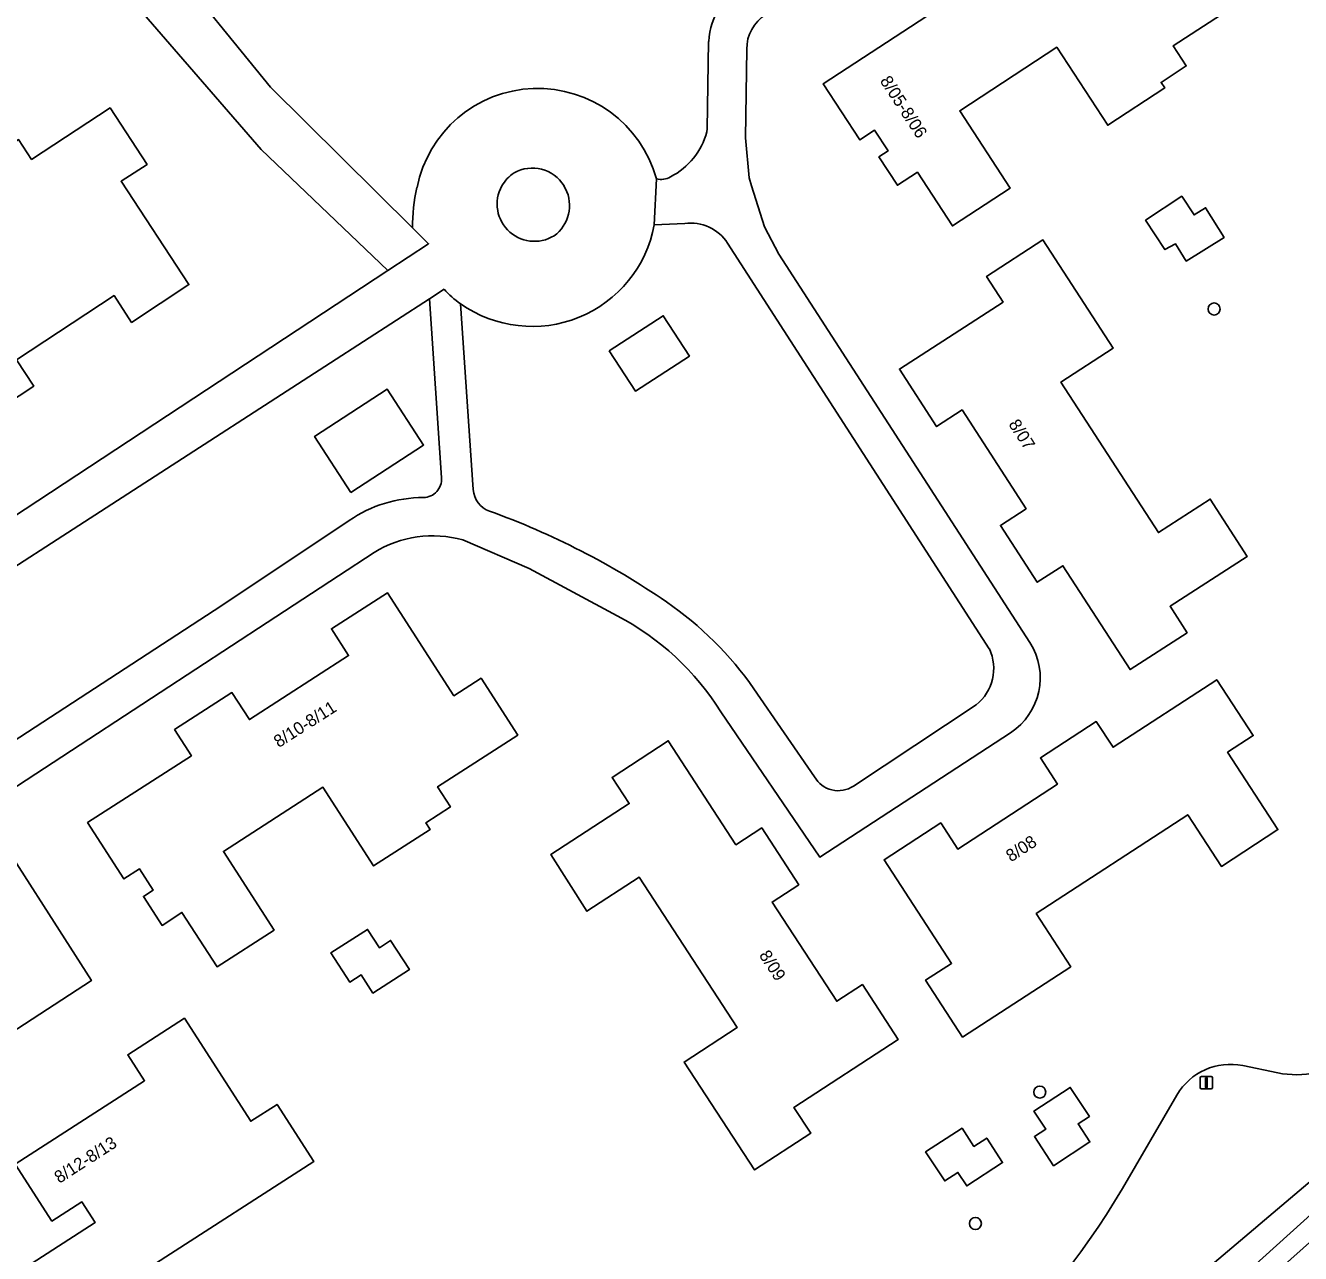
# Model space of a CAD drawing. Extents: x 159451 to 160664, y 388402 to 389723.
# Drawn here: x 160043.7 to 160146.8, y 389163.7 to 389263 of the extents above; entities that cross this region are included whole.
import ezdxf

# ---------------------------------------------------------------- set-up
doc = ezdxf.new("R2010")
doc.units = 0
for name, color, linetype in [('IMGEO_Boom', 7, 'Continuous'), ('IMGEO_Erf', 7, 'Continuous'), ('IMGEO_Grasland_overig', 7, 'Continuous'), ('IMGEO_Groenvoorziening', 7, 'Continuous'), ('IMGEO_Lichtmast', 7, 'Continuous'), ('IMGEO_Loofbos', 7, 'Continuous'), ('IMGEO_Oever', 7, 'Continuous'), ('IMGEO_Pand', 7, 'Continuous'), ('IMGEO_Pand_nummerreeks', 7, 'Continuous'), ('IMGEO_Rijbaan_lokaal_gesloten', 7, 'Continuous'), ('IMGEO_Rijbaan_lokaal_open', 7, 'Continuous'), ('IMGEO_Terreindeel_gesloten', 7, 'Continuous'), ('IMGEO_Voetpad_gesloten', 7, 'Continuous'), ('IMGEO_Waterloop', 7, 'Continuous')]:
    doc.layers.add(name, color=color, linetype=linetype)

msp = doc.modelspace()

# ---------------------------------------------------------------- linework, layer by layer
at = {"layer": 'IMGEO_Boom'}
for centre in [(160139.77, 389240.04), (160125.68, 389176.75), (160120.48, 389166.13)]:
    msp.add_circle(centre, 0.489, dxfattribs=at)
at = {"layer": 'IMGEO_Erf'}
for points in [[(160062.76, 389252.92), (160050.65, 389266.93)], [(160142.81, 389265.45), (160136.46, 389261.3), (160137.52, 389259.69), (160135.49, 389258.36), (160135.79, 389257.91), (160131.18, 389254.89), (160127.06, 389261.2), (160119.21, 389256.07), (160123.3, 389249.81), (160118.62, 389246.75), (160115.79, 389251.09), (160114.18, 389250.04), (160112.68, 389252.33), (160113.43, 389252.82), (160112.33, 389254.49), (160111.15, 389253.71), (160108.18, 389258.25), (160116.55, 389263.72)], [(160102, 389261.03), (160101.9, 389253.88), (160102.19, 389250.64), (160102.39, 389250), (160103.43, 389246.67), (160104.59, 389244.47), (160124.88, 389213.09)], [(160034.2, 389217.64), (160072.99, 389243.15), (160062.76, 389252.92)], [(160091.53, 389215.25), (160084.42, 389219.08), (160079.06, 389221.38)], [(160071.89, 389220.37), (160040.16, 389199.62), (160049.04, 389185.76), (160029.31, 389172.93), (160027.27, 389171.6), (160021.26, 389180.85)], [(160123.31, 389205.79), (160107.92, 389195.73), (160099.9, 389207.48)], [(160036.46, 389157.9), (160049.34, 389166.2), (160048.27, 389167.87), (160045.85, 389166.32), (160042.88, 389170.93), (160053.34, 389177.67), (160051.98, 389179.77), (160056.55, 389182.72), (160061.92, 389174.39), (160064.05, 389175.76), (160067.02, 389171.15), (160054.21, 389162.9)], [(160142.09, 389178.89), (160144.92, 389178.3)], [(160132.36, 389168.97), (160136.77, 389176.51)]]:
    msp.add_lwpolyline(points, dxfattribs=at)
for points in [[(160051.44, 389250.36), (160056.92, 389242.01), (160052.29, 389238.96), (160050.87, 389241.12), (160042.98, 389235.94), (160044.38, 389233.81), (160039.78, 389230.79), (160038.4, 389232.89), (160030.09, 389227.43), (160027.07, 389232.03), (160027.53, 389232.34), (160024.89, 389236.34), (160026.55, 389237.42), (160023.67, 389241.8), (160028.24, 389244.79), (160032.39, 389238.47), (160040.35, 389243.69), (160036.26, 389249.91), (160040.87, 389252.94), (160041.2, 389252.44), (160043.16, 389253.73), (160044.21, 389252.13), (160050.55, 389256.29), (160053.54, 389251.73)], [(160134.23, 389247.21), (160137.16, 389249.15), (160138.16, 389247.64), (160139.09, 389248.22), (160140.58, 389245.83), (160137.52, 389243.91), (160136.64, 389245.31), (160135.8, 389244.84)], [(160114.34, 389235.18), (160122.72, 389240.6), (160121.38, 389242.68), (160125.94, 389245.63), (160131.61, 389236.87), (160127.39, 389234.14), (160135.27, 389221.97), (160139.46, 389224.68), (160142.45, 389220.05), (160136.21, 389216.01), (160137.59, 389213.88), (160132.98, 389210.9), (160127.55, 389219.29), (160125.48, 389217.95), (160122.5, 389222.55), (160124.58, 389223.89), (160119.41, 389231.88), (160117.34, 389230.54)], [(160048.73, 389198.53), (160057.12, 389203.94), (160055.76, 389206.05), (160060.4, 389209.04), (160061.81, 389206.85), (160069.83, 389212.03), (160068.43, 389214.2), (160072.96, 389217.11), (160078.33, 389208.78), (160080.53, 389210.2), (160083.49, 389205.61), (160077.01, 389201.43), (160078.06, 389199.8), (160076.06, 389198.51), (160076.41, 389197.97), (160071.85, 389195.03), (160067.75, 389201.39), (160059.71, 389196.2), (160063.8, 389189.85), (160059.19, 389186.88), (160056.36, 389191.27), (160054.75, 389190.22), (160053.24, 389192.56), (160054.04, 389193.08), (160052.93, 389194.79), (160051.67, 389193.98)], [(160113.1, 389195.53), (160117.68, 389198.51), (160119.06, 389196.39), (160127.11, 389201.64), (160125.73, 389203.76), (160130.25, 389206.7), (160131.61, 389204.62), (160139.98, 389210.08), (160142.93, 389205.56), (160140.86, 389204.22), (160144.93, 389197.97), (160140.36, 389194.99), (160137.64, 389199.16), (160125.4, 389191.18), (160128.19, 389186.88), (160119.44, 389181.19), (160116.45, 389185.8), (160118.56, 389187.15)], [(160093.32, 389194.12), (160089.09, 389191.36), (160086.16, 389195.94), (160092.5, 389200.07), (160091.12, 389202.18), (160095.66, 389205.14), (160101.13, 389196.74), (160103.22, 389198.1), (160106.21, 389193.51), (160104.05, 389192.1), (160109.28, 389184.09), (160111.35, 389185.44), (160114.25, 389181.01), (160105.82, 389175.51), (160107.18, 389173.42), (160102.63, 389170.46), (160096.94, 389179.18), (160101.23, 389181.98)], [(160068.4, 389188.01), (160071.36, 389189.9), (160072.31, 389188.42), (160073.22, 389189.01), (160074.74, 389186.65), (160071.79, 389184.75), (160070.84, 389186.23), (160069.92, 389185.64)], [(160125.21, 389175.22), (160128.15, 389177.13), (160129.7, 389174.78), (160128.78, 389174.19), (160129.74, 389172.72), (160126.8, 389170.8), (160125.25, 389173.15), (160126.17, 389173.74)], [(160119.4, 389173.83), (160120.36, 389172.36), (160121.4, 389173.03), (160122.68, 389171.05), (160119.78, 389169.17), (160119.07, 389170.26), (160118.01, 389169.57), (160116.46, 389171.92)]]:
    msp.add_lwpolyline(points, close=True, dxfattribs=at)
for centre, radius, start, end in [((160105.31, 389261.06), 3.31, 122.4721, 180.4297), ((160076.64, 389212.6), 9.11, 74.6376, 121.4412), ((160081.39, 389195.93), 21.82, 31.964, 62.3071), ((160120.43, 389210.23), 5.29, 302.9705, 32.6845), ((160141.08, 389173.99), 5, 78.3578, 149.7367), ((160146.43, 389185.65), 7.5, 258.3604, 305.7362), ((160080.54, 389199.21), 60, 292.4572, 329.7288)]:
    msp.add_arc(centre, radius, start, end, dxfattribs=at)
at = {"layer": 'IMGEO_Grasland_overig'}
for centre, radius, start, end in [((160084.86, 389248.51), 3.03, 123.2192, 150.5671), ((160084.67, 389248.41), 3.02, 31.7007, 119.2412), ((160084.84, 389248.52), 3.01, 150.605, 306.9536), ((160084.63, 389248.41), 3.05, 311.2675, 31.4443)]:
    msp.add_arc(centre, radius, start, end, dxfattribs=at)
at = {"layer": 'IMGEO_Groenvoorziening'}
for points in [[(160096.99, 389246.95), (160094.53, 389246.84)], [(160121.6, 389212.58), (160100.46, 389245.36)], [(160077.34, 389226.4), (160076.35, 389240.87), (160068.36, 389235.7), (160036.5, 389215.12)], [(160078.87, 389240.47), (160079.9, 389225.44)], [(160034.78, 389207.9), (160038.43, 389202.32), (160059.58, 389216.09), (160069.88, 389222.95)], [(160102.58, 389209.35), (160107.47, 389202.22)], [(160110.62, 389201.47), (160120.55, 389208.05)]]:
    msp.add_lwpolyline(points, dxfattribs=at)
for points in [[(160090.89, 389236.66), (160095.26, 389239.49), (160097.37, 389236.23), (160093.01, 389233.4)], [(160070.01, 389225.22), (160067.07, 389229.74), (160072.95, 389233.56), (160075.89, 389229.04)]]:
    msp.add_lwpolyline(points, close=True, dxfattribs=at)
for centre, radius, start, end in [((160097.49, 389243.45), 3.53, 32.7801, 98.2227), ((160084.66, 389248.67), 10.04, 234.7811, 349.539), ((160075.84, 389226.3), 1.5, 271.3812, 3.8511), ((160081.9, 389225.58), 2, 183.9538, 249.8911), ((160075.84, 389214.25), 10.55, 89.8332, 124.4314), ((160059.62, 389163.99), 63.5, 55.5826, 70.1199), ((160079.89, 389193.56), 27.64, 34.8129, 55.5935), ((160118.17, 389210.99), 3.79, 308.901, 24.8278), ((160109.4, 389203.33), 2.22, 209.994, 303.2571)]:
    msp.add_arc(centre, radius, start, end, dxfattribs=at)
at = {"layer": 'IMGEO_Lichtmast'}
for p, q in [((160138.65, 389177.11), (160138.65, 389177.91)), ((160138.65, 389177.91), (160138.65, 389177.11)), ((160138.75, 389178.01), (160139.54, 389178.01)), ((160139.54, 389178.01), (160138.75, 389178.01)), ((160139.64, 389177.91), (160139.64, 389177.11)), ((160139.64, 389177.11), (160139.64, 389177.91)), ((160139.54, 389177.01), (160138.75, 389177.01)), ((160138.75, 389177.01), (160139.54, 389177.01))]:
    msp.add_line(p, q, dxfattribs=at)
msp.add_lwpolyline([(160139.07, 389177.89), (160139.22, 389177.89), (160139.22, 389177.14), (160139.07, 389177.14), (160139.07, 389177.89)], dxfattribs=at)
for centre, start, end in [((160138.75, 389177.91), 90, 180), ((160138.75, 389177.91), 90, 180), ((160139.54, 389177.91), 0, 90), ((160139.54, 389177.91), 360, 90), ((160138.75, 389177.11), 180, 270), ((160138.75, 389177.11), 180, 270), ((160139.54, 389177.11), 270, 0), ((160139.54, 389177.11), 270, 0)]:
    msp.add_arc(centre, 0.1, start, end, dxfattribs=at)
at = {"layer": 'IMGEO_Loofbos'}
for points in [[(160053.14, 389283.56), (160048.18, 389280.3), (160049.4, 389278.45), (160050.84, 389276.24), (160052.78, 389272.29), (160054.86, 389268.6), (160063.52, 389257.98), (160075, 389246.59)], [(160120.48, 389146.62), (160165.95, 389185.12), (160168.11, 389187.1), (160178.43, 389197.48), (160182.22, 389202.77), (160187.6, 389212.28), (160189.05, 389215.64), (160191.05, 389219.31), (160193.43, 389222.84), (160196.19, 389226.54), (160202.65, 389234.04), (160207.42, 389238.61), (160216.26, 389246.29), (160219.05, 389248.41), (160219.75, 389249.51), (160219.77, 389250), (160219.9, 389252.39), (160219.6, 389253.79), (160215.62, 389259.16), (160212.09, 389263.94)], [(160098.77, 389254.36), (160098.81, 389254.61), (160098.92, 389261.66)], [(160144.92, 389178.3), (160142.09, 389178.89)], [(160136.77, 389176.51), (160132.36, 389168.97)]]:
    msp.add_lwpolyline(points, dxfattribs=at)
for centre, radius, start, end in [((160105.32, 389261.22), 6.41, 122.2326, 176.0667), ((160085.11, 389247.93), 9.94, 15.2828, 168.82), ((160093.21, 389255.85), 5.76, 297.188, 345.0559), ((160095.06, 389252.03), 1.52, 256.3148, 300.8302), ((160088.89, 389246.76), 13.89, 167.1286, 180.711), ((160141.08, 389173.99), 5, 78.3578, 149.7367), ((160146.43, 389185.65), 7.5, 258.3604, 305.7362), ((160080.54, 389199.21), 60, 292.4572, 329.7288)]:
    msp.add_arc(centre, radius, start, end, dxfattribs=at)
at = {"layer": 'IMGEO_Oever'}
for points in [[(160221.19, 389262.82), (160220.17, 389262.1), (160215.62, 389259.16), (160219.6, 389253.79), (160219.9, 389252.39), (160219.77, 389250), (160219.75, 389249.51), (160219.05, 389248.41), (160216.26, 389246.29), (160207.42, 389238.61), (160202.65, 389234.04), (160196.19, 389226.54), (160193.43, 389222.84), (160191.05, 389219.31), (160189.05, 389215.64), (160187.6, 389212.28), (160182.22, 389202.77), (160178.43, 389197.48), (160168.11, 389187.1), (160165.95, 389185.12), (160120.48, 389146.62)], [(160141.78, 389161.6), (160180.78, 389196.82), (160189.59, 389211.89), (160195.07, 389221.31), (160205.58, 389234.29), (160221.41, 389248.19), (160221.64, 389253.13), (160218.92, 389258.62), (160220.25, 389259.47), (160223.48, 389253.63), (160223.4, 389251.74), (160223.25, 389247.53), (160218.77, 389243.44), (160206.52, 389233.05), (160197.1, 389221), (160191.93, 389213.59), (160188.84, 389207.95), (160185.28, 389201.38), (160182.15, 389196.01), (160165.55, 389180.72), (160142.96, 389160.56)]]:
    msp.add_lwpolyline(points, dxfattribs=at)
at = {"layer": 'IMGEO_Pand'}
for points in [[(160116.55, 389263.72), (160108.18, 389258.25), (160111.15, 389253.71), (160112.33, 389254.49), (160113.43, 389252.82), (160112.68, 389252.33), (160114.18, 389250.04), (160115.79, 389251.09), (160118.62, 389246.75), (160123.3, 389249.81), (160119.21, 389256.07), (160127.06, 389261.2), (160131.18, 389254.89), (160135.79, 389257.91), (160135.49, 389258.36), (160137.52, 389259.69), (160136.46, 389261.3), (160142.81, 389265.45)], [(160054.21, 389162.9), (160067.02, 389171.15), (160064.05, 389175.76), (160061.92, 389174.39), (160056.55, 389182.72), (160051.98, 389179.77), (160053.34, 389177.67), (160042.88, 389170.93), (160045.85, 389166.32), (160048.27, 389167.87), (160049.34, 389166.2), (160036.46, 389157.9)]]:
    msp.add_lwpolyline(points, dxfattribs=at)
for points in [[(160030.09, 389227.43), (160038.4, 389232.89), (160039.78, 389230.79), (160044.38, 389233.81), (160042.98, 389235.94), (160050.87, 389241.12), (160052.29, 389238.96), (160056.92, 389242.01), (160051.44, 389250.36), (160053.54, 389251.73), (160050.55, 389256.29), (160044.21, 389252.13), (160043.16, 389253.73), (160041.2, 389252.44), (160040.87, 389252.94), (160036.26, 389249.91), (160040.35, 389243.69), (160032.39, 389238.47), (160028.24, 389244.79), (160023.67, 389241.8), (160026.55, 389237.42), (160024.89, 389236.34), (160027.53, 389232.34), (160027.07, 389232.03)], [(160137.52, 389243.91), (160140.58, 389245.83), (160139.09, 389248.22), (160138.16, 389247.64), (160137.16, 389249.15), (160134.23, 389247.21), (160135.8, 389244.84), (160136.64, 389245.31)], [(160132.98, 389210.9), (160137.59, 389213.88), (160136.21, 389216.01), (160142.45, 389220.05), (160139.46, 389224.68), (160135.27, 389221.97), (160127.39, 389234.14), (160131.61, 389236.87), (160125.94, 389245.63), (160121.38, 389242.68), (160122.72, 389240.6), (160114.34, 389235.18), (160117.34, 389230.54), (160119.41, 389231.88), (160124.58, 389223.89), (160122.5, 389222.55), (160125.48, 389217.95), (160127.55, 389219.29)], [(160059.19, 389186.88), (160063.8, 389189.85), (160059.71, 389196.2), (160067.75, 389201.39), (160071.85, 389195.03), (160076.41, 389197.97), (160076.06, 389198.51), (160078.06, 389199.8), (160077.01, 389201.43), (160083.49, 389205.61), (160080.53, 389210.2), (160078.33, 389208.78), (160072.96, 389217.11), (160068.43, 389214.2), (160069.83, 389212.03), (160061.81, 389206.85), (160060.4, 389209.04), (160055.76, 389206.05), (160057.12, 389203.94), (160048.73, 389198.53), (160051.67, 389193.98), (160052.93, 389194.79), (160054.04, 389193.08), (160053.24, 389192.56), (160054.75, 389190.22), (160056.36, 389191.27)], [(160119.44, 389181.19), (160128.19, 389186.88), (160125.4, 389191.18), (160137.64, 389199.16), (160140.36, 389194.99), (160144.93, 389197.97), (160140.86, 389204.22), (160142.93, 389205.56), (160139.98, 389210.08), (160131.61, 389204.62), (160130.25, 389206.7), (160125.73, 389203.76), (160127.11, 389201.64), (160119.06, 389196.39), (160117.68, 389198.51), (160113.1, 389195.53), (160118.56, 389187.15), (160116.45, 389185.8)], [(160102.63, 389170.46), (160107.18, 389173.42), (160105.82, 389175.51), (160114.25, 389181.01), (160111.35, 389185.44), (160109.28, 389184.09), (160104.05, 389192.1), (160106.21, 389193.51), (160103.22, 389198.1), (160101.13, 389196.74), (160095.66, 389205.14), (160091.12, 389202.18), (160092.5, 389200.07), (160086.16, 389195.94), (160089.09, 389191.36), (160093.32, 389194.12), (160101.23, 389181.98), (160096.94, 389179.18)], [(160071.79, 389184.75), (160074.74, 389186.65), (160073.22, 389189.01), (160072.31, 389188.42), (160071.36, 389189.9), (160068.4, 389188.01), (160069.92, 389185.64), (160070.84, 389186.23)], [(160126.8, 389170.8), (160129.74, 389172.72), (160128.78, 389174.19), (160129.7, 389174.78), (160128.15, 389177.13), (160125.21, 389175.22), (160126.17, 389173.74), (160125.25, 389173.15)], [(160119.78, 389169.17), (160122.68, 389171.05), (160121.4, 389173.03), (160120.36, 389172.36), (160119.4, 389173.83), (160116.46, 389171.92), (160118.01, 389169.57), (160119.07, 389170.26)]]:
    msp.add_lwpolyline(points, close=True, dxfattribs=at)
at = {"layer": 'IMGEO_Rijbaan_lokaal_gesloten'}
msp.add_lwpolyline([(160050.65, 389266.93), (160062.76, 389252.92), (160072.99, 389243.15), (160076.29, 389245.32), (160075, 389246.59), (160063.52, 389257.98), (160054.86, 389268.6), (160052.78, 389272.29), (160050.84, 389276.24), (160049.4, 389278.45), (160043.54, 389274.71), (159994.77, 389243.39), (159993.51, 389242.58), (159975.92, 389231.28)], dxfattribs=at)
at = {"layer": 'IMGEO_Rijbaan_lokaal_open'}
for points in [[(160094.53, 389246.84), (160094.7, 389250.55)], [(160075, 389246.59), (160076.29, 389245.32), (160072.99, 389243.15), (160034.2, 389217.64)], [(160036.5, 389215.12), (160068.36, 389235.7), (160076.35, 389240.87), (160077.54, 389241.64)], [(160021.26, 389180.85), (160027.27, 389171.6), (160029.31, 389172.93), (160049.04, 389185.76), (160040.16, 389199.62), (160038.43, 389202.32), (160034.78, 389207.9)]]:
    msp.add_lwpolyline(points, dxfattribs=at)
for centre, radius, start, end in [((160085.11, 389247.93), 9.94, 15.2828, 168.82), ((160084.86, 389248.51), 3.03, 123.2192, 150.5671), ((160084.67, 389248.41), 3.02, 31.7007, 119.2412), ((160084.84, 389248.52), 3.01, 150.605, 306.9536), ((160084.63, 389248.41), 3.05, 311.2675, 31.4443), ((160088.89, 389246.76), 13.89, 167.1286, 180.711), ((160084.66, 389248.67), 10.04, 234.7811, 349.539), ((160083.57, 389247.19), 8.2, 222.6199, 235.0508)]:
    msp.add_arc(centre, radius, start, end, dxfattribs=at)
at = {"layer": 'IMGEO_Terreindeel_gesloten'}
for points in [[(160090.89, 389236.66), (160093.01, 389233.4), (160097.37, 389236.23), (160095.26, 389239.49)], [(160070.01, 389225.22), (160075.89, 389229.04), (160072.95, 389233.56), (160067.07, 389229.74)]]:
    msp.add_lwpolyline(points, close=True, dxfattribs=at)
at = {"layer": 'IMGEO_Voetpad_gesloten'}
for points in [[(160098.92, 389261.66), (160098.81, 389254.61), (160098.77, 389254.36)], [(160124.88, 389213.09), (160104.59, 389244.47), (160103.43, 389246.67), (160102.39, 389250), (160102.19, 389250.64), (160101.9, 389253.88), (160102, 389261.03)], [(160094.7, 389250.55), (160094.53, 389246.84), (160096.99, 389246.95)], [(160100.46, 389245.36), (160121.6, 389212.58)], [(160077.54, 389241.64), (160076.35, 389240.87), (160077.34, 389226.4)], [(160079.9, 389225.44), (160078.87, 389240.47)], [(160069.88, 389222.95), (160059.58, 389216.09), (160038.43, 389202.32), (160040.16, 389199.62), (160071.89, 389220.37)], [(160079.06, 389221.38), (160084.42, 389219.08), (160091.53, 389215.25)], [(160107.47, 389202.22), (160102.58, 389209.35)], [(160120.55, 389208.05), (160110.62, 389201.47)], [(160099.9, 389207.48), (160107.92, 389195.73), (160123.31, 389205.79)]]:
    msp.add_lwpolyline(points, dxfattribs=at)
for centre, radius, start, end in [((160105.32, 389261.22), 6.41, 122.2326, 176.0667), ((160105.31, 389261.06), 3.31, 122.4721, 180.4297), ((160093.21, 389255.85), 5.76, 297.188, 345.0559), ((160095.06, 389252.03), 1.52, 256.3148, 300.8302), ((160097.49, 389243.45), 3.53, 32.7801, 98.2227), ((160083.57, 389247.19), 8.2, 222.6199, 235.0508), ((160075.84, 389226.3), 1.5, 271.3812, 3.8511), ((160081.9, 389225.58), 2, 183.9538, 249.8911), ((160075.84, 389214.25), 10.55, 89.8332, 124.4314), ((160059.62, 389163.99), 63.5, 55.5826, 70.1199), ((160076.64, 389212.6), 9.11, 74.6376, 121.4412), ((160079.89, 389193.56), 27.64, 34.8129, 55.5935), ((160081.39, 389195.93), 21.82, 31.964, 62.3071), ((160120.43, 389210.23), 5.29, 302.9705, 32.6845), ((160118.17, 389210.99), 3.79, 308.901, 24.8278), ((160109.4, 389203.33), 2.22, 209.994, 303.2571)]:
    msp.add_arc(centre, radius, start, end, dxfattribs=at)
at = {"layer": 'IMGEO_Waterloop'}
msp.add_lwpolyline([(160142.96, 389160.56), (160165.55, 389180.72), (160182.15, 389196.01), (160185.28, 389201.38), (160188.84, 389207.95), (160191.93, 389213.59), (160197.1, 389221), (160206.52, 389233.05), (160218.77, 389243.44), (160223.25, 389247.53), (160223.4, 389251.74), (160223.48, 389253.63), (160220.25, 389259.47), (160218.92, 389258.62), (160221.64, 389253.13), (160221.41, 389248.19), (160205.58, 389234.29), (160195.07, 389221.31), (160189.59, 389211.89), (160180.78, 389196.82), (160141.78, 389161.6)], dxfattribs=at)

# ---------------------------------------------------------------- texts
at = {"layer": 'IMGEO_Pand_nummerreeks'}
for s, rotation, p in [('8/05-8/06', 303.0668, (160112.73, 389258.48)), ('8/07', 302.8437, (160123.12, 389230.73)), ('8/10-8/11', 32.5124, (160064.18, 389204.55)), ('8/08', 33.0674, (160123.36, 389195.31)), ('8/09', 303.0763, (160102.96, 389187.81)), ('8/12-8/13', 32.8427, (160046.45, 389169.33))]:
    msp.add_text(s, height=1, rotation=rotation, dxfattribs=at).set_placement(p)

doc.saveas('drawing.dxf')
